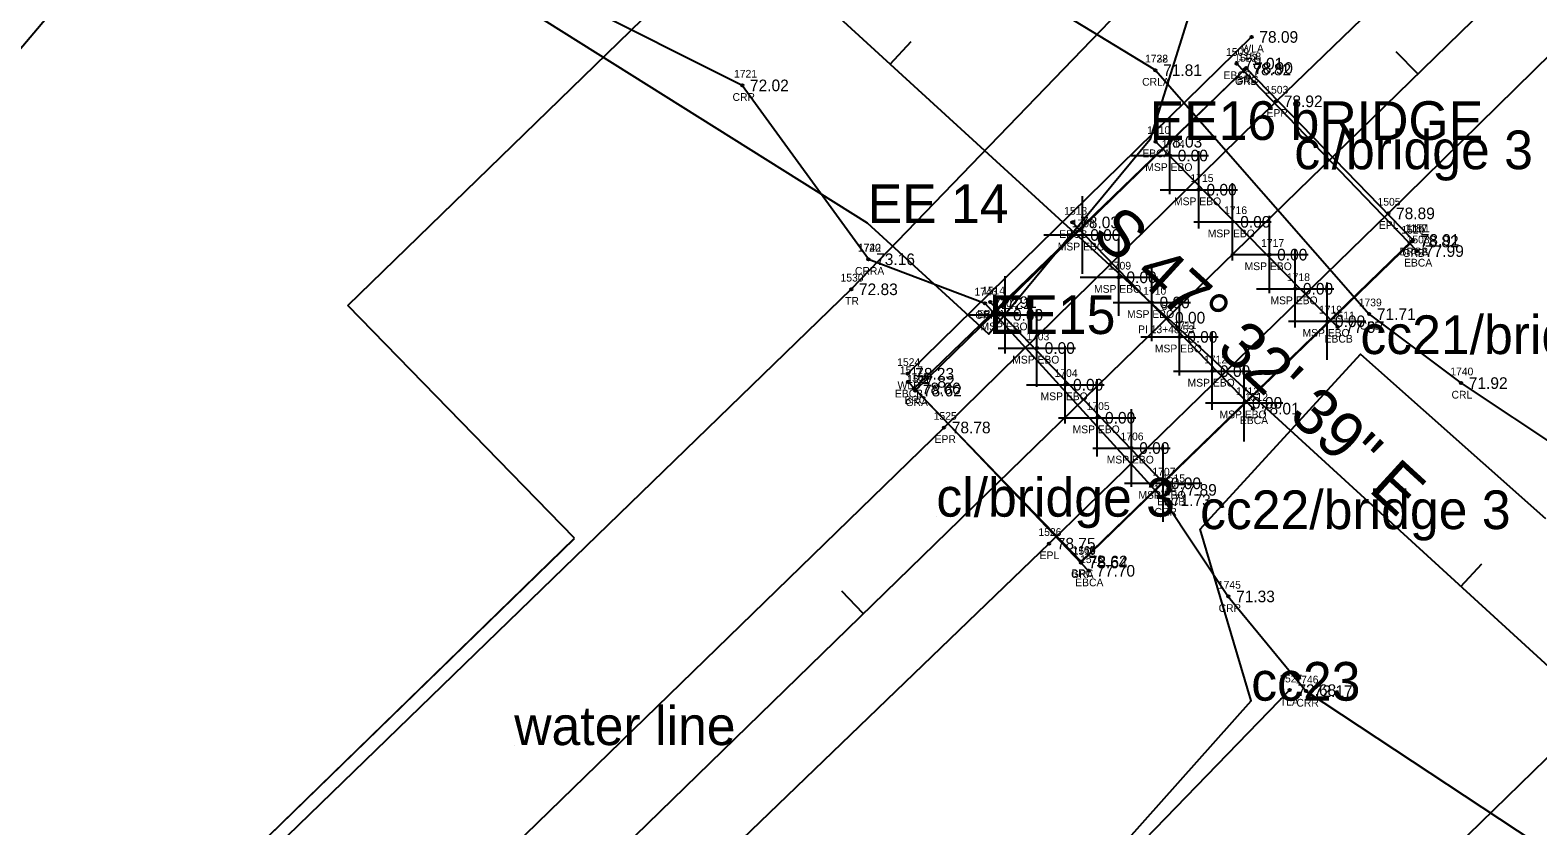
# Model space of a CAD drawing. Extents: x 2500794 to 2511032, y 910653 to 917533.
# Drawn here: x 2505136.3 to 2505331.2, y 912905 to 913007.8 of the extents above; entities that cross this region are included whole.
import ezdxf

# ---------------------------------------------------------------- set-up
doc = ezdxf.new("R2010")
doc.units = 0
for name, color, linetype in [('Default', 7, 'Continuous'), ('RD_EX_BldgApp', 7, 'Continuous'), ('RD_EX_Bridge', 7, 'Continuous'), ('RD_EX_Bridge_txCode', 7, 'Continuous'), ('RD_EX_DV_Prop', 7, 'Continuous'), ('RD_EX_GuardRail', 7, 'Continuous'), ('RD_EX_GuardRail_txCode', 7, 'Continuous'), ('RD_EX_H2O_txCode', 7, 'Continuous'), ('RD_EX_H2O_WetLd', 7, 'Continuous'), ('RD_EX_Misc', 7, 'Continuous'), ('RD_EX_Misc_txCode', 7, 'Continuous'), ('RD_EX_Road', 7, 'Continuous'), ('RD_EX_Road_txCode', 7, 'Continuous'), ('RD_EX_RW', 7, 'Continuous'), ('RD_EX_TX_Bridge_ELEV', 7, 'Continuous'), ('RD_EX_TX_GuardRail_ELEV', 7, 'Continuous'), ('RD_EX_TX_H2O_ELEV', 7, 'Continuous'), ('RD_EX_TX_Misc_ELEV', 7, 'Continuous'), ('RD_EX_TX_Road_ELEV', 7, 'Continuous'), ('RD_EX_TX_UT_ELEV', 7, 'Continuous'), ('RD_EX_TX_VEG_ELEV', 7, 'Continuous'), ('RD_EX_UT_txCode', 7, 'Continuous'), ('RD_EX_VEG', 7, 'Continuous'), ('RD_EX_VEG_txCode', 7, 'Continuous'), ('RD_HC_Cl', 7, 'Continuous'), ('RD_HC_Data', 7, 'Continuous'), ('RD_HC_Data_Tic', 7, 'Continuous'), ('RD_HC_Survey_ELEV', 7, 'Continuous'), ('RD_HC_txCode', 7, 'Continuous'), ('RD_SMD_Locator', 7, 'Continuous')]:
    doc.layers.add(name, color=color, linetype=linetype)

# ---------------------------------------------------------------- blocks, each defined once
blk = doc.blocks.new('POINT_DISPLAY')
at = {"layer": 'Default'}
blk.add_line((0, 0), (0, 0), dxfattribs=at)
blk = doc.blocks.new('Wetlands')
at = {"layer": 'Default'}
for points in [[(636342.944, 231940.182), (636350.209, 231928.858), (636354.738, 231922.099), (636343.337, 231906.608), (636341.382, 231900.373), (636336.102, 231894.003), (636332.117, 231897.645), (636320.479, 231904.936), (636305.393, 231904.66), (636298.923, 231897.016), (636294.296, 231884.265), (636283.587, 231877.605), (636286.971, 231867.991), (636291.686, 231861.221), (636288.9, 231854.468), (636279.39, 231852.849), (636269.749, 231853.613), (636263.179, 231852.028), (636258.651, 231849.987), (636250.174, 231852.919), (636244.941, 231856.37), (636269.687, 231880.898), (636308.974, 231919.839), (636399.189, 232007.15)], [(636373.86, 231876.593), (636322.695, 231826.15), (636292.001, 231795.727), (636288.552, 231801.204), (636276.275, 231810.411), (636280.758, 231816.983), (636294.104, 231832.432), (636311.497, 231848.926), (636330.531, 231866.041), (636344.713, 231881.969), (636343.035, 231887.6), (636348.3, 231893.346), (636354.376, 231887.946)]]:
    blk.add_lwpolyline(points, dxfattribs=at)

msp = doc.modelspace()

# ---------------------------------------------------------------- linework, layer by layer
at = {"layer": 'RD_EX_BldgApp'}
msp.add_line((2505294.2, 913006.91), (2505249.72, 912963.39), dxfattribs=at)
at = {"layer": 'RD_EX_Bridge'}
for p, q in [((2505315.62, 912979.24), (2505292.27, 913003.47)), ((2505281.8, 912993.37), (2505305.34, 912969.41)), ((2505294.4, 912958.88), (2505271.04, 912982.94)), ((2505260.41, 912972.64), (2505283.68, 912948.38)), ((2505273.12, 912937.92), (2505249.79, 912962.33))]:
    msp.add_line(p, q, dxfattribs=at)
msp.add_lwpolyline([(2505315.06, 912980.68), (2505293.52, 913002.89), (2505250.57, 912961.49), (2505272.15, 912939.12), (2505315.06, 912980.68)], dxfattribs=at)
at = {"layer": 'RD_EX_DV_Prop'}
msp.add_line((2503534.53, 911315.65), (2505206.65, 912942.11), dxfattribs=at)
at = {"layer": 'RD_EX_GuardRail'}
for p, q in [((2505250.72, 912961.21), (2505293.3, 913002.71)), ((2505272.13, 912938.99), (2505314.95, 912980.49))]:
    msp.add_line(p, q, dxfattribs=at)
at = {"layer": 'RD_EX_H2O_txCode'}
for points in [[(2505244.66, 912978.18), (2505228.35, 913000.65), (2505184.75, 913022.53), (2505151.8, 913063.53), (2505112.58, 913101.46), (2505066, 913175.02), (2505056.4, 913208.97), (2505062.51, 913229.15), (2505037.95, 913240.94)], [(2505281.76, 913002.61), (2505244.38, 913025.41), (2505203.22, 913061.75), (2505174.11, 913086.82), (2505132.24, 913122.64), (2505091.24, 913184.3), (2505079.55, 913206.6), (2505087.26, 913223.44), (2505124.53, 913212.76)], [(2505281.76, 913002.61), (2505309.4, 912971.1), (2505321.28, 912962.18), (2505334.8, 912953.22), (2505369.77, 912915.95), (2505384.9, 912864.42), (2505373.2, 912815.64), (2505382.57, 912803.97), (2505437.95, 912778.47), (2505481, 912757.61), (2505533.06, 912704.94)], [(2505244.66, 912978.18), (2505259.72, 912972.49), (2505282.9, 912947.05), (2505291.19, 912934.61), (2505301.24, 912922.37), (2505337.69, 912898.33), (2505350.73, 912862.58), (2505336.39, 912800.89), (2505361.15, 912786.5), (2505403.95, 912734.79), (2505467.35, 912720.29), (2505522.39, 912682.34)]]:
    msp.add_lwpolyline(points, dxfattribs=at)
at = {"layer": 'RD_EX_Misc'}
for p, q in [((2505283.65, 912986.59), (2505283.65, 912996.59)), ((2505287.37, 912982.17), (2505287.37, 912992.17)), ((2505278.65, 912991.59), (2505288.65, 912991.59)), ((2505272.34, 912976.32), (2505272.34, 912986.32)), ((2505282.37, 912987.17), (2505292.37, 912987.17)), ((2505291.73, 912978.02), (2505291.73, 912988.02)), ((2505286.73, 912983.02), (2505296.73, 912983.02)), ((2505296.5, 912973.78), (2505296.5, 912983.78)), ((2505267.34, 912981.32), (2505277.34, 912981.32)), ((2505277.02, 912970.85), (2505277.02, 912980.85)), ((2505291.5, 912978.78), (2505301.5, 912978.78)), ((2505299.84, 912969.37), (2505299.84, 912979.37)), ((2505281.3, 912967.6), (2505281.3, 912977.6)), ((2505262.35, 912966), (2505262.35, 912976)), ((2505272.02, 912975.85), (2505282.02, 912975.85)), ((2505303.98, 912965.17), (2505303.98, 912975.17)), ((2505276.3, 912972.6), (2505286.3, 912972.6)), ((2505284.88, 912963.15), (2505284.88, 912973.15)), ((2505294.84, 912974.37), (2505304.84, 912974.37)), ((2505257.35, 912971), (2505267.35, 912971)), ((2505266.45, 912961.71), (2505266.45, 912971.71)), ((2505289.12, 912958.73), (2505289.12, 912968.73)), ((2505298.98, 912970.17), (2505308.98, 912970.17)), ((2505270.12, 912956.97), (2505270.12, 912966.97)), ((2505279.88, 912968.15), (2505289.88, 912968.15)), ((2505261.45, 912966.71), (2505271.45, 912966.71)), ((2505284.12, 912963.73), (2505294.12, 912963.73)), ((2505293.25, 912954.63), (2505293.25, 912964.63)), ((2505265.12, 912961.97), (2505275.12, 912961.97)), ((2505274.25, 912952.7), (2505274.25, 912962.7)), ((2505288.25, 912959.63), (2505298.25, 912959.63)), ((2505269.25, 912957.7), (2505279.25, 912957.7)), ((2505278.67, 912948.79), (2505278.67, 912958.79)), ((2505273.67, 912953.79), (2505283.67, 912953.79)), ((2505282.76, 912944.23), (2505282.76, 912954.23)), ((2505277.76, 912949.23), (2505287.76, 912949.23))]:
    msp.add_line(p, q, dxfattribs=at)
at = {"layer": 'RD_EX_Road'}
for points in [[(2505356.25, 913055.37), (2505297.36, 912998.59), (2505254.44, 912956.44), (2505177.06, 912881.21), (2505102.21, 912808.73), (2505026.72, 912735.2), (2504956.07, 912666.21), (2504882.83, 912595.14), (2504825.46, 912547.52), (2504807.83, 912522.24), (2504732.55, 912448.69), (2504654.06, 912372.59), (2504585.1, 912305.45), (2504533.51, 912254.98)], [(2505370.6, 913041.78), (2505311.87, 912984.11), (2505268.01, 912941.43), (2505190.92, 912867.21), (2505116.28, 912794.43), (2505039.14, 912719.03), (2504973.12, 912654.77), (2504957.32, 912639.49), (2504897.44, 912581.22), (2504858.98, 912543.75), (2504838.29, 912523.7), (2504810.7, 912496.65), (2504795.8, 912482.32), (2504747.07, 912434.9), (2504696.6, 912386.17), (2504686.81, 912376.67), (2504668.39, 912358.37), (2504598.36, 912290.29), (2504547.08, 912240.34)]]:
    msp.add_lwpolyline(points, dxfattribs=at)
at = {"layer": 'RD_EX_RW'}
for p, q in [((2505177.37, 912972.22), (2505320.74, 913111.67)), ((2505281.96, 912864.7), (2505425.33, 913004.15)), ((2505206.66, 912942.12), (2505177.37, 912972.22)), ((2504517.34, 912271.63), (2505206.66, 912942.12))]:
    msp.add_line(p, q, dxfattribs=at)
at = {"layer": 'RD_EX_VEG'}
for points in [[(2505339.13, 913074.53), (2505242.44, 912974.3), (2505088.02, 912824.67), (2504935.82, 912672.7), (2504815.59, 912550.95), (2504817.4, 912591.81)], [(2505299.12, 912922.5), (2505143.93, 912762.37), (2505067.63, 912689.26), (2504988.4, 912634.77), (2505004.57, 912602.97)]]:
    msp.add_lwpolyline(points, dxfattribs=at)
at = {"layer": 'RD_HC_Cl'}
for p, q in [((2504540.35, 912247.97), (2505598.79, 913277.5)), ((2505236.1, 913013.81), (2505353.01, 912906.84))]:
    msp.add_line(p, q, dxfattribs=at)
at = {"layer": 'RD_HC_Data_Tic'}
for p, q in [((2505247.49, 913003.39), (2505250.19, 913006.34)), ((2505315.69, 913002.13), (2505312.9, 913005)), ((2505321.27, 912935.89), (2505323.97, 912938.84)), ((2505244, 912932.41), (2505241.21, 912935.27))]:
    msp.add_line(p, q, dxfattribs=at)
at = {"layer": 'RD_SMD_Locator'}
for centre in [(2505294.2, 913006.91), (2505281.76, 913002.61), (2505281.76, 913002.61), (2505292.27, 913003.47), (2505293.3, 913002.71), (2505293.52, 913002.89), (2505228.35, 913000.65), (2505297.36, 912998.59), (2505281.8, 912993.37), (2505283.65, 912991.59), (2505287.37, 912987.17), (2505311.87, 912984.11), (2505271.04, 912982.94), (2505291.73, 912983.02), (2505272.34, 912981.32), (2505314.95, 912980.49), (2505315.06, 912980.68), (2505315.06, 912980.68), (2505296.5, 912978.78), (2505315.62, 912979.24), (2505244.66, 912978.18), (2505244.66, 912978.18), (2505277.02, 912975.85), (2505299.84, 912974.37), (2505242.44, 912974.3), (2505259.72, 912972.49), (2505260.41, 912972.64), (2505281.3, 912972.6), (2505262.35, 912971), (2505309.4, 912971.1), (2505303.98, 912970.17), (2505305.34, 912969.41), (2505266.45, 912966.71), (2505284.88, 912968.15), (2505249.72, 912963.39), (2505289.12, 912963.73), (2505249.79, 912962.33), (2505250.57, 912961.49), (2505250.72, 912961.21), (2505270.12, 912961.97), (2505321.28, 912962.18), (2505293.25, 912959.63), (2505294.4, 912958.88), (2505274.25, 912957.7), (2505254.44, 912956.44), (2505278.67, 912953.79), (2505282.76, 912949.23), (2505283.68, 912948.38), (2505282.9, 912947.05), (2505268.01, 912941.43), (2505272.13, 912938.99), (2505272.15, 912939.12), (2505273.12, 912937.92), (2505291.19, 912934.61), (2505299.12, 912922.5), (2505301.24, 912922.37)]:
    msp.add_circle(centre, 0.15, dxfattribs=at)

# ---------------------------------------------------------------- block references
at = {"layer": 'Default', "xscale": 3.937007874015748, "yscale": 3.937007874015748}
for name, p in [('Wetlands', (0, 0)), ('POINT_DISPLAY', (2505281.03, 912993.6)), ('POINT_DISPLAY', (2505281.03, 912993.6)), ('POINT_DISPLAY', (2505299.72, 912989.82)), ('POINT_DISPLAY', (2505299.72, 912989.82)), ('POINT_DISPLAY', (2505244.56, 912982.86)), ('POINT_DISPLAY', (2505244.56, 912982.86)), ('POINT_DISPLAY', (2505260.24, 912968.52)), ('POINT_DISPLAY', (2505260.24, 912968.52)), ('POINT_DISPLAY', (2505308.27, 912965.93)), ('POINT_DISPLAY', (2505308.27, 912965.93)), ('POINT_DISPLAY', (2505253.44, 912944.92)), ('POINT_DISPLAY', (2505253.44, 912944.92)), ('POINT_DISPLAY', (2505287.54, 912943.31)), ('POINT_DISPLAY', (2505287.54, 912943.31)), ('POINT_DISPLAY', (2505294.15, 912921.14)), ('POINT_DISPLAY', (2505294.15, 912921.14)), ('POINT_DISPLAY', (2505198.87, 912915.4)), ('POINT_DISPLAY', (2505198.87, 912915.4))]:
    msp.add_blockref(name, p, dxfattribs=at)
at = {"layer": 'RD_EX_H2O_WetLd', "xscale": 3.937007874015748, "yscale": 3.937007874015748}
msp.add_blockref('Wetlands', (0, 0), dxfattribs=at)

# ---------------------------------------------------------------- texts
at = {"layer": 'Default'}
for s, p in [('EE16 bRIDGE', (2505281.03, 912993.6)), ('EE16 bRIDGE', (2505281.03, 912993.6)), ('cl/bridge 3', (2505299.72, 912989.82)), ('cl/bridge 3', (2505299.72, 912989.82)), ('EE 14', (2505244.56, 912982.86)), ('EE 14', (2505244.56, 912982.86)), ('EE15', (2505260.24, 912968.52)), ('EE15', (2505260.24, 912968.52)), ('cc21/bridge 3', (2505308.27, 912965.93)), ('cc21/bridge 3', (2505308.27, 912965.93)), ('cl/bridge 3', (2505253.44, 912944.92)), ('cl/bridge 3', (2505253.44, 912944.92)), ('cc22/bridge 3', (2505287.54, 912943.31)), ('cc22/bridge 3', (2505287.54, 912943.31)), ('cc23', (2505294.15, 912921.14)), ('cc23', (2505294.15, 912921.14)), ('water line', (2505198.87, 912915.4)), ('water line', (2505198.87, 912915.4))]:
    msp.add_text(s, height=5, dxfattribs=at).set_placement(p)
at = {"layer": 'RD_EX_Bridge_txCode'}
for s, p in [('1509', (2505290.89, 913004.47)), ('1158', (2505292.46, 913003.89)), ('EBCB', (2505290.57, 913001.47)), ('BRC', (2505292.27, 913000.89)), ('1510', (2505280.7, 912994.37)), ('EBCA', (2505280.08, 912991.37)), ('1513', (2505269.97, 912983.94)), ('1157', (2505313.99, 912981.68)), ('1161', (2505314.25, 912981.68)), ('EBCB', (2505269.33, 912980.94)), ('1508', (2505314.24, 912980.24)), ('BRCA', (2505313.32, 912978.68)), ('BRCB', (2505313.33, 912978.68)), ('EBCA', (2505313.91, 912977.24)), ('1514', (2505259.35, 912973.64)), ('EBCA', (2505258.7, 912970.64)), ('1511', (2505304.56, 912970.41)), ('EBCB', (2505303.64, 912967.41)), ('1517', (2505248.73, 912963.33)), ('1159', (2505249.51, 912962.49)), ('EBCB', (2505248.09, 912960.33)), ('1512', (2505293.34, 912959.88)), ('BRC', (2505249.32, 912959.49)), ('EBCA', (2505292.69, 912956.88)), ('1515', (2505282.62, 912949.38)), ('EBCB', (2505281.98, 912946.38)), ('1160', (2505271.02, 912940.12)), ('1516', (2505272.03, 912938.92)), ('BRC', (2505270.9, 912937.12)), ('EBCA', (2505271.4, 912935.92))]:
    msp.add_text(s, height=1, dxfattribs=at).set_placement(p)
at = {"layer": 'RD_EX_GuardRail_txCode'}
for s, p in [('1522', (2505291.96, 913003.71)), ('GRB', (2505292.05, 913000.71)), ('1520', (2505313.56, 912981.49)), ('GRB', (2505313.7, 912978.49)), ('1521', (2505249.66, 912962.21)), ('GRA', (2505249.46, 912959.21)), ('1519', (2505271.07, 912939.99)), ('GRA', (2505270.86, 912936.99))]:
    msp.add_text(s, height=1, dxfattribs=at).set_placement(p)
at = {"layer": 'RD_EX_H2O_txCode'}
for s, p in [('1722', (2505280.42, 913003.61)), ('1738', (2505280.42, 913003.61)), ('1721', (2505227.29, 913001.65)), ('CRLA', (2505280.05, 913000.61)), ('CRLA', (2505280.05, 913000.61)), ('CRR', (2505227.1, 912998.65)), ('1720', (2505243.28, 912979.18)), ('1742', (2505243.32, 912979.18)), ('CRRA', (2505242.92, 912976.18)), ('CRRA', (2505242.92, 912976.18)), ('1743', (2505258.37, 912973.49)), ('1739', (2505308.05, 912972.1)), ('CRR', (2505258.47, 912970.49)), ('CRL', (2505308.17, 912969.1)), ('1740', (2505319.89, 912963.18)), ('CRL', (2505320.05, 912960.18)), ('1744', (2505281.55, 912948.05)), ('CRR', (2505281.65, 912945.05)), ('1745', (2505289.84, 912935.61)), ('CRR', (2505289.94, 912932.61)), ('1746', (2505299.87, 912923.37)), ('CRR', (2505299.99, 912920.37))]:
    msp.add_text(s, height=1, dxfattribs=at).set_placement(p)
at = {"layer": 'RD_EX_Misc_txCode'}
for s, p in [('1714', (2505282.59, 912992.59)), ('MSP EBO', (2505280.46, 912989.59)), ('1715', (2505286.3, 912988.17)), ('MSP EBO', (2505284.17, 912985.17)), ('1716', (2505290.64, 912984.02)), ('1708', (2505270.95, 912982.32)), ('MSP EBO', (2505288.53, 912981.02)), ('1717', (2505295.43, 912979.78)), ('MSP EBO', (2505269.14, 912979.32)), ('1709', (2505275.64, 912976.85)), ('MSP EBO', (2505293.3, 912976.78)), ('MSP EBO', (2505273.83, 912973.85)), ('1710', (2505280.19, 912973.6)), ('1718', (2505298.77, 912975.37)), ('1702', (2505260.97, 912972)), ('MSP EBO', (2505296.64, 912972.37)), ('MSP EBO', (2505278.1, 912970.6)), ('1719', (2505302.92, 912971.17)), ('MSP EBO', (2505259.15, 912969)), ('1703', (2505265.07, 912967.71)), ('1711', (2505284.1, 912969.15)), ('MSP EBO', (2505300.78, 912968.17)), ('MSP EBO', (2505281.69, 912966.15)), ('MSP EBO', (2505263.25, 912964.71)), ('1712', (2505288.06, 912964.73)), ('1704', (2505268.73, 912962.97)), ('MSP EBO', (2505266.92, 912959.97)), ('MSP EBO', (2505285.92, 912961.73)), ('1713', (2505292.19, 912960.63)), ('1705', (2505272.87, 912958.7)), ('MSP EBO', (2505290.05, 912957.63)), ('MSP EBO', (2505271.06, 912955.7)), ('1706', (2505277.26, 912954.79)), ('MSP EBO', (2505275.47, 912951.79)), ('1707', (2505281.38, 912950.23)), ('MSP EBO', (2505279.57, 912947.23))]:
    msp.add_text(s, height=1, dxfattribs=at).set_placement(p)
at = {"layer": 'RD_EX_Road_txCode'}
for s, p in [('1503', (2505295.97, 912999.59)), ('EPR', (2505296.13, 912996.59)), ('1505', (2505310.48, 912985.11)), ('EPL', (2505310.66, 912982.11)), ('1525', (2505253.1, 912957.44)), ('EPR', (2505253.22, 912954.44)), ('1526', (2505266.64, 912942.43)), ('EPL', (2505266.8, 912939.43))]:
    msp.add_text(s, height=1, dxfattribs=at).set_placement(p)
at = {"layer": 'RD_EX_TX_Bridge_ELEV'}
for s, p in [('78.01', (2505293.27, 913002.72)), ('78.90', (2505294.52, 913002.14)), ('78.03', (2505282.8, 912992.62)), ('78.03', (2505272.04, 912982.19)), ('78.91', (2505316.06, 912979.93)), ('78.91', (2505316.06, 912979.93)), ('77.99', (2505316.62, 912978.49)), ('77.91', (2505261.41, 912971.89)), ('77.97', (2505306.34, 912968.66)), ('77.82', (2505250.79, 912961.58)), ('78.66', (2505251.57, 912960.74)), ('78.01', (2505295.4, 912958.13)), ('77.89', (2505284.68, 912947.63)), ('78.62', (2505273.15, 912938.37)), ('77.70', (2505274.12, 912937.17))]:
    msp.add_text(s, height=1.5, dxfattribs=at).set_placement(p)
at = {"layer": 'RD_EX_TX_GuardRail_ELEV'}
for s, p in [('78.82', (2505294.3, 913001.96)), ('78.82', (2505315.95, 912979.74)), ('78.62', (2505251.72, 912960.46)), ('78.64', (2505273.13, 912938.24))]:
    msp.add_text(s, height=1.5, dxfattribs=at).set_placement(p)
at = {"layer": 'RD_EX_TX_H2O_ELEV'}
for s, p in [('71.81', (2505282.76, 913001.86)), ('71.81', (2505282.76, 913001.86)), ('72.02', (2505229.35, 912999.9)), ('73.16', (2505245.66, 912977.43)), ('73.16', (2505245.66, 912977.43)), ('72.21', (2505260.72, 912971.74)), ('71.71', (2505310.4, 912970.35)), ('71.92', (2505322.28, 912961.43)), ('71.73', (2505283.9, 912946.3)), ('71.33', (2505292.19, 912933.86)), ('72.17', (2505302.24, 912921.62))]:
    msp.add_text(s, height=1.5, dxfattribs=at).set_placement(p)
at = {"layer": 'RD_EX_TX_Misc_ELEV'}
for p in [(2505284.65, 912990.84), (2505288.37, 912986.42), (2505292.73, 912982.27), (2505273.34, 912980.57), (2505297.5, 912978.03), (2505278.02, 912975.1), (2505300.84, 912973.62), (2505282.3, 912971.85), (2505263.35, 912970.25), (2505304.98, 912969.42), (2505285.88, 912967.4), (2505267.45, 912965.96), (2505290.12, 912962.98), (2505271.12, 912961.22), (2505294.25, 912958.88), (2505275.25, 912956.95), (2505279.67, 912953.04), (2505283.76, 912948.48)]:
    msp.add_text('0.00', height=1.5, dxfattribs=at).set_placement(p)
at = {"layer": 'RD_EX_TX_Road_ELEV'}
for s, p in [('78.92', (2505298.36, 912997.84)), ('78.89', (2505312.87, 912983.36)), ('78.78', (2505255.44, 912955.69)), ('78.75', (2505269.01, 912940.68))]:
    msp.add_text(s, height=1.5, dxfattribs=at).set_placement(p)
at = {"layer": 'RD_EX_TX_UT_ELEV'}
for s, p in [('78.09', (2505295.2, 913006.16)), ('78.23', (2505250.72, 912962.64))]:
    msp.add_text(s, height=1.5, dxfattribs=at).set_placement(p)
at = {"layer": 'RD_EX_TX_VEG_ELEV'}
for s, p in [('72.83', (2505243.44, 912973.55)), ('72.68', (2505300.12, 912921.75))]:
    msp.add_text(s, height=1.5, dxfattribs=at).set_placement(p)
at = {"layer": 'RD_EX_UT_txCode'}
for s, p in [('WLA', (2505292.89, 913004.91)), ('1524', (2505248.38, 912964.39)), ('WLB', (2505248.43, 912961.39))]:
    msp.add_text(s, height=1, dxfattribs=at).set_placement(p)
at = {"layer": 'RD_EX_VEG_txCode'}
for s, p in [('1530', (2505241.06, 912975.3)), ('TR', (2505241.65, 912972.3)), ('1527', (2505297.77, 912923.5)), ('TLA', (2505297.86, 912920.5))]:
    msp.add_text(s, height=1, dxfattribs=at).set_placement(p)
at = {"layer": 'RD_HC_Data'}
msp.add_text('S 47%%d 32\' 39" E', height=6, rotation=317.5441, dxfattribs=at).set_placement((2505273.29, 912981.14))
at = {"layer": 'RD_HC_Survey_ELEV'}
msp.add_text('0.00', height=1.5, dxfattribs=at).set_placement((2505284.3, 912969.88))
at = {"layer": 'RD_HC_txCode'}
for s, p in [('54', (2505282.56, 912971.63)), ('PI 13+48.53', (2505279.52, 912968.63))]:
    msp.add_text(s, height=1, dxfattribs=at).set_placement(p)

doc.saveas('drawing.dxf')
